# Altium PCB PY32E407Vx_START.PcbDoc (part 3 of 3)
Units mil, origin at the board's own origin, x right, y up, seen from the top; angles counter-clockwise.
Board outline 5249.65 x 2929.09 mil, 4 copper layers (Top Layer, GND, POWER, Bottom Layer); 239 components, 235 nets, 934 pads, 637 vias.
Unrouted connection lines stored in the file: 84.
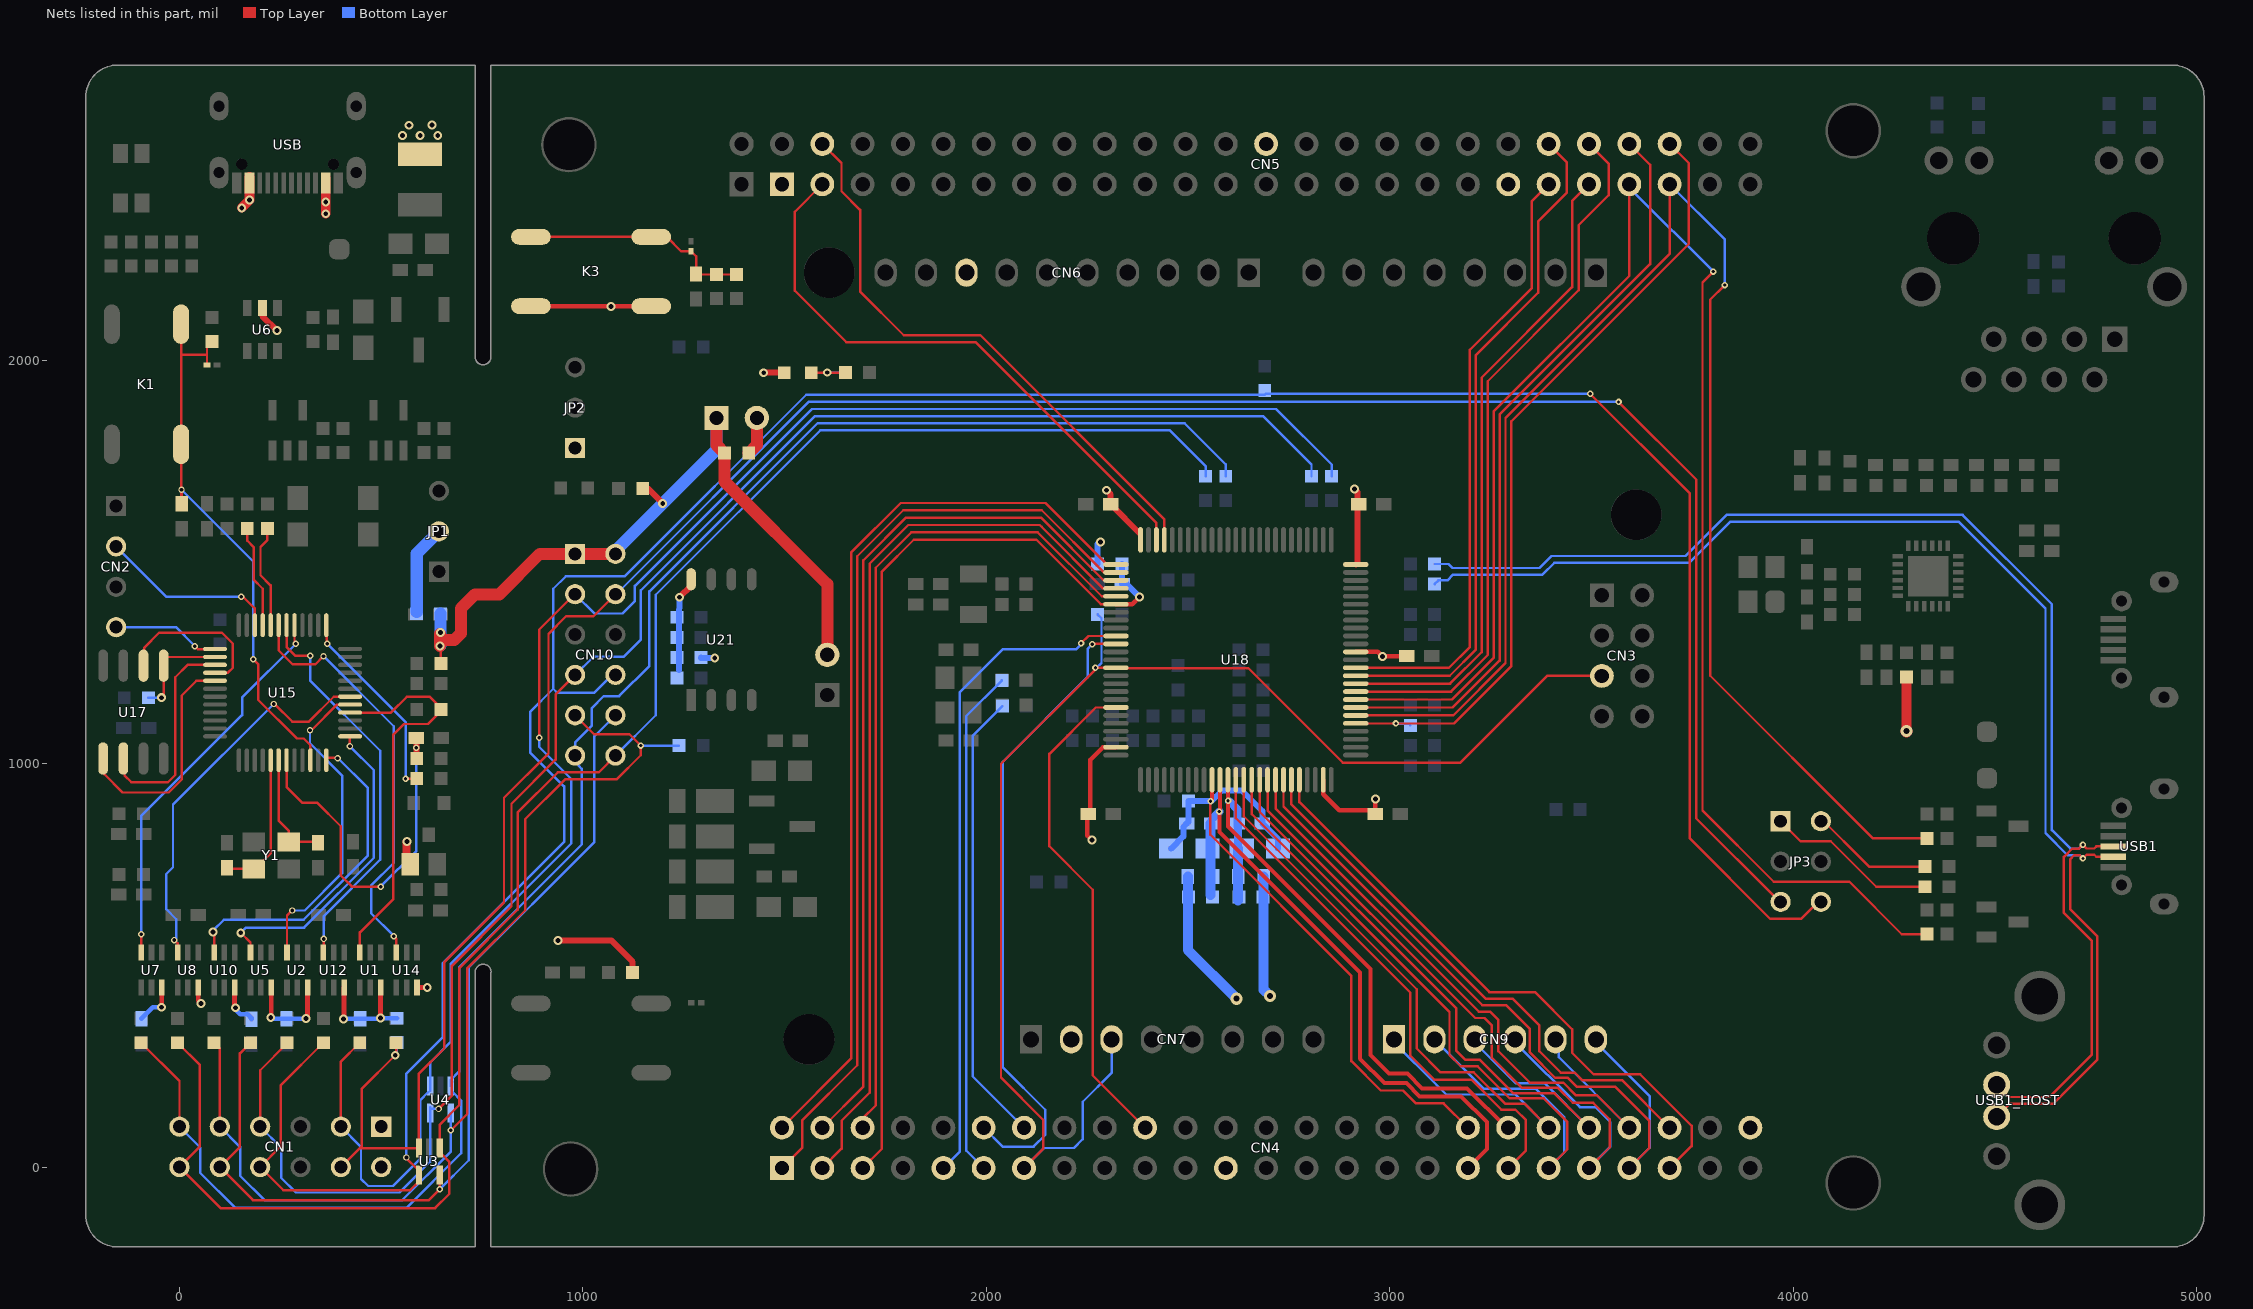
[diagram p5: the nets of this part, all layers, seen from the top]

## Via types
v1: diameter 22, hole 12, Top Layer to Bottom Layer, tented both sides, 398 vias
v2: diameter 16, hole 8, Top Layer to Bottom Layer, tented both sides, 111 vias
v3: diameter 20, hole 10, Top Layer to Bottom Layer, tented both sides, 54 vias
v4: diameter 16, hole 9, Top Layer to Bottom Layer, tented both sides, 41 vias
v5: diameter 30, hole 15, Top Layer to Bottom Layer, tented both sides, 15 vias
v6: diameter 20, hole 10, Top Layer to Bottom Layer, 9 vias
v7: diameter 15, hole 8, Top Layer to Bottom Layer, tented both sides, 5 vias
v8: diameter 16, hole 8, Top Layer to Bottom Layer, 3 vias
v9: diameter 20, hole 12, Top Layer to Bottom Layer, tented both sides, 1 vias

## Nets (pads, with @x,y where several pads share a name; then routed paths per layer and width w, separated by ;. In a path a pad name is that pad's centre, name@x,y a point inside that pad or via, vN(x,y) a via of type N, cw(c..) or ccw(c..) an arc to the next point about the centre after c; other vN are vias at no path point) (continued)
PD8: CN5.46 R58.2 U18.55 | length 1977.9
  Top Layer w6: U18.55@2915.24,1099.61 2915.58,1099.28 3014.72,1099.28 v2(3014.83,1099.38) 3014.93,1099.28 3158.28,1099.28 3301,1241.99 3301,1848.33 3740.4,2287.73 3740.4,2488.25 CN5.46@3693.11,2535.55
  Bottom Layer w6: v2(3014.83,1099.38) 3015.62,1098.59 3046.5,1098.59 R58.2@3050.5,1094.59
PD9: CN5.45 R93.1 U18.56 | length 3787.8
  Top Layer w6: U18.56@2915.24,1119.29 3156.8,1119.29 3286.29,1248.78 3286.29,1856.09 3693.11,2262.91 CN5.45@3693.11,2435.55 ; v2(3829.84,2185.75) 3793.7,2149.61 3793.7,1217.69 4196.8,814.59 R93.1@4330.5,814.59 4338,814.59 R93.1@4343,819.59
  Bottom Layer w6: CN5.45@3693.11,2435.55 3829.84,2298.81 v2(3829.84,2185.75)
PD10: CN5.44 U18.57 | length 1860.7
  Top Layer w6: U18.57@2915.24,1138.98 3155.29,1138.98 3271.57,1255.27 3271.57,1864.73 3644.7,2237.86 3644.7,2483.95 CN5.44@3593.11,2535.55
PD11: CN5.43 R85.1 U18.58 | length 4034.5
  Top Layer w6: U18.58@2915.24,1158.66 3153.67,1158.66 3256.86,1261.85 3256.86,1872.32 3593.11,2208.57 CN5.43@3593.11,2435.55 ; v2(3801.32,2219.18) 3774.5,2192.36 3774.5,883.29 3950.9,706.89 4138.6,706.89 4268.4,577.09 R85.1@4330.5,577.09
  Bottom Layer w6: CN5.43@3593.11,2435.55 3601.15,2435.55 3601.15,2419.35 v2(3801.32,2219.18)
PD12: CN5.42 U18.59 | length 1775.2
  Top Layer w6: U18.59@2915.24,1178.35 3151.56,1178.35 3242.14,1268.94 3242.14,1947.44 3467.9,2173.19 3467.9,2334.67 3541.7,2408.47 3541.7,2486.95 CN5.42@3493.11,2535.55
PD13: CN5.41 U18.60 | length 1613.9
  Top Layer w6: U18.60@2915.24,1198.03 3149.14,1198.03 3227.43,1276.32 3227.43,1956.62 3451.5,2180.69 3451.5,2393.94 CN5.41@3493.11,2435.55
PD14: CN5.40 U18.61 | length 1689.1
  Top Layer w6: U18.61@2915.24,1217.72 3147.93,1217.72 3212.71,1282.51 3212.71,2012.16 ; 3212.77,2012.16 3367.22,2166.62 3367.22,2343.8 3437.8,2414.37 3437.8,2490.85 CN5.40@3393.11,2535.55
PD15: CN5.39 U18.62 | length 1531.4
  Top Layer w6: U18.62@2915.24,1237.4 3146.31,1237.4 3198,1289.09 3198,2025.49 3351.5,2178.99 3351.5,2393.94 CN5.39@3393.11,2435.55
PE0: CN5.4 U18.97 | length 1443.5
  Top Layer w6: CN5.4@1593.11,2535.55 1640.59,2488.07 1640.59,2418.41 1686.8,2372.2 1686.8,2169.49 1794.99,2061.3 1984.79,2061.3 2440.83,1605.26 U18.97@2440.83,1554.33
PE1: CN5.3 U18.98 | length 1468.2
  Top Layer w6: CN5.3@1593.11,2435.55 1525,2367.44 1525,2171.89 1652.6,2044.29 1972.8,2044.29 2421.15,1595.94 U18.98@2421.15,1554.33
PE2: CN4.2 U18.1 | length 2266.5
  Top Layer w6: CN4.2@1493.11,97.55 1664.52,268.96 1664.52,1522.61 1787.68,1645.77 2146.58,1645.77 2299.04,1493.31 U18.1@2320.76,1493.31
PE3: CN4.1 U18.2 | length 2345.4
  Top Layer w6: CN4.1@1493.11,-2.45 1543,47.44 1543,115.59 1679.79,252.38 1679.79,1513.68 1793.68,1627.58 2136.94,1627.58 2290.88,1473.63 U18.2@2320.76,1473.63
PE4: CN4.4 U18.3 | length 2182.4
  Top Layer w6: CN4.4@1593.11,97.55 1695.05,199.49 1695.05,1503.98 1800.45,1609.38 2135,1609.38 2290.44,1453.94 U18.3@2320.76,1453.94
PE5: CN4.3 U18.4 | length 2261.5
  Top Layer w6: CN4.3@1593.11,-2.45 1641.1,45.54 1641.1,114.85 1710.32,184.07 1710.32,1495.3 1806.2,1591.18 2132.13,1591.18 2136.59,1586.72 2289.05,1434.26 U18.4@2320.76,1434.26
PE6: CN4.6 U18.5 | length 2098.2
  Top Layer w6: CN4.6@1693.11,97.55 1693.11,120.4 1725.59,152.88 1725.59,1485.09 1813.49,1572.99 2127.1,1572.99 2285.52,1414.57 U18.5@2320.76,1414.57
PE7: CN4.37 U18.38 | length 1352.4
  Top Layer w6: U18.38@2618,959.85 2618,914.55 2618,864.29 3050.5,431.79 3050.5,275.86 3109.75,216.61 3201.69,216.61 3276.2,142.09 3311,142.09 3336.8,116.29 3336.8,41.24 CN4.37@3293.11,-2.45
PE8: CN4.40 CN9.1 U18.39 | length 1729.7
  Top Layer w6: U18.39@2637.69,959.85 2637.69,869.22 3066.2,440.71 3066.2,294.09 3125.58,234.71 3207.48,234.71 3285.1,157.09 3333.56,157.09 CN4.40@3393.11,97.55
  Bottom Layer w6: CN9.1@3010.11,316.55 3010.11,309.05 3116.3,202.85 3139.26,179.89 3310.76,179.89 CN4.40@3393.11,97.55
PE9: CN4.39 CN9.2 U18.40 | length 1923.1
  Top Layer w6: U18.40@2657.37,959.85 2657.37,874.64 3147.4,384.61 3147.4,277.79 3175.21,249.99 3217.21,249.99 3296.6,170.59 3380.6,170.59 3439.6,111.59 3439.6,44.04 CN4.39@3393.11,-2.45
  Bottom Layer w6: CN9.2@3110.11,316.55 3232.16,194.49 3360.3,194.49 3432.3,122.49 3432.3,36.74 CN4.39@3393.11,-2.45
PE10: CN4.42 CN9.3 U18.41 | length 1659.5
  Top Layer w6: U18.41@2677.06,959.85 2677.06,880.24 3164.41,392.89 3164.41,287.77 3186.78,265.4 3222.99,265.4 3305.8,182.59 3408.06,182.59 CN4.42@3493.11,97.55
  Bottom Layer w6: CN9.3@3210.11,316.55 3210.11,309.05 3311.06,208.09 3382.56,208.09 CN4.42@3493.11,97.55
PE11: CN4.41 CN9.4 U18.42 | length 1891.2
  Top Layer w6: U18.42@2696.74,959.85 2696.74,883.79 3211.23,369.3 3234.4,369.3 3252.45,351.24 3252.45,270.94 3327.2,196.19 3416.2,196.19 3453.1,159.29 3503.5,159.29 3544.56,118.24 3544.56,49 CN4.41@3493.11,-2.45
  Bottom Layer w6: CN9.4@3310.11,316.55 3310.11,309.05 3470.76,148.39 3509,148.39 3546.2,111.19 3546.2,50.64 CN4.41@3493.11,-2.45
PE12: CN4.44 CN9.5 U18.43 | length 1615.7
  Top Layer w6: U18.43@2716.43,959.85 2716.43,888.76 3219.84,385.36 3247.64,385.36 3268.51,364.48 3268.51,286.98 3346.7,208.79 3429.7,208.79 3460.1,178.39 3512.26,178.39 CN4.44@3593.11,97.55
  Bottom Layer w6: CN9.5@3410.11,316.55 3418.11,308.55 3418.11,272.55 CN4.44@3593.11,97.55
PE13: CN4.43 CN9.6 U18.44 | length 1861.8
  Top Layer w6: U18.44@2736.11,959.85 2736.11,893.98 3228.68,401.42 3287.68,401.42 3346.7,342.39 3346.7,283.79 3409.6,220.89 3441.1,220.89 3463.3,198.69 3558.6,198.69 3642.1,115.19 3642.1,46.54 CN4.43@3593.11,-2.45
  Bottom Layer w6: CN9.6@3510.11,316.55 3510.11,309.05 3643.4,175.75 3643.4,47.84 CN4.43@3593.11,-2.45
PE14: CN4.46 U18.45 | length 1367.6
  Top Layer w6: U18.45@2755.8,959.85 2755.8,898.79 3237.12,417.48 3303.72,417.48 3370.4,350.79 3370.4,286.99 3423.7,233.69 3458.2,233.69 3477.1,214.79 3575.86,214.79 CN4.46@3693.11,97.55
PE15: CN4.45 U18.46 | length 1521.2
  Top Layer w6: U18.46@2775.48,959.85 2775.48,904.31 3246.26,433.54 3359.46,433.54 3451.8,341.19 3451.8,282.79 3504.7,229.89 3619.9,229.89 3747.4,102.39 3747.4,51.84 CN4.45@3693.11,-2.45
PF0: CN4.11 R40.1 | length 1262.9
  Bottom Layer w6: CN4.11@1993.11,-2.45 1949.92,40.73 1949.92,1117.72 R40.1@2038.2,1205.99
PF1: CN4.14 R41.1 | length 1127.9
  Bottom Layer w6: R41.1@2039.3,1142.19 1965.68,1068.57 1965.68,224.97 CN4.14@2093.11,97.55
PF2: CN4.20 U18.19 | length 1237.3
  Top Layer w6: U18.19@2320.76,1138.98 2270.85,1138.98 2155.8,1023.94 2155.8,794.99 2263.5,687.29 2263.5,227.15 CN4.20@2393.11,97.55
PF3: CN4.9 U18.10 | length 1642.7
  Top Layer w6: v2(2234.42,1298.19) 2252.38,1316.15 U18.10@2320.76,1316.15
  Bottom Layer w6: CN4.9@1893.11,-2.45 1934.17,38.61 1934.17,1177.16 2040.61,1283.59 2195.53,1283.59 2223.07,1283.59 2232.84,1293.36 2234.42,1294.94 v2(2234.42,1298.19)
PF4: CN4.12 U18.11 | length 1594
  Top Layer w6: v2(2262.22,1295.61) 2263.08,1296.46 U18.11@2320.76,1296.46
  Bottom Layer w6: CN4.12@1993.11,97.55 2039.86,50.79 2116.9,50.79 2145.6,79.49 2145.6,141.99 2040.7,246.89 2040.7,1004.35 2250.45,1214.1 2250.45,1283.84 v2(2262.22,1295.61)
PF5: CN3.5 CN4.13 CN7.3 R54.2 U18.14 | length 3438.5
  Top Layer w6: CN4.13@2093.11,-2.45 2140.2,44.64 2140.2,117.39 2035.9,221.69 2035.9,999.39 2272.2,1235.69 v2@2270.63,1237.27 ; v2(2270.1,1237.27) v2@2270.63,1237.27 ; CN3.5@3525.12,1217.14 3389.25,1217.14 3174.5,1002.39 2882.92,1002.39 2648.72,1236.59 2321.57,1236.59 U18.14@2320.76,1237.4 2320.62,1237.27 v2@2270.63,1237.27
  Bottom Layer w6: CN4.13@2093.11,-2.45 2142.75,47.19 2216.7,47.19 2238.7,69.19 2238.7,161.89 2310.11,233.3 CN7.3@2310.11,316.55 ; v2(2270.1,1237.27) 2272.77,1237.27 2285,1249.49 2285,1360.09 R54.2@2275.5,1369.59
PYLK_KEY: C5.2 K1.2 R14.1 U11.1 U15.10 | length 1409.8
  Top Layer w6: K1.2@4,2089 4,2013.39 ; v4(5,1678.59) 5.5,1678.09 C5.2@5.5,1644 ; C5.2@5.5,1643.81 C5.2@5.5,1644 ; U11.1@68.2,1988 68.2,2013.35 ; R14.1@68.2,2038.7 68.2,2013.35 ; v2(182.8,1258.49) 194.9,1246.39 194.9,1158.25 291.15,1062 307.84,1062 323.91,1045.92 323.91,1008.86 U15.10@324.4,1008.37 ; 4,2013.39 K1.2@4,1791 4,1645.5 C5.2@5.5,1644 ; 4,2013.39 4.04,2013.35 68.2,2013.35
  Bottom Layer w6: v4(5,1678.59) 182.8,1500.79 v2(182.8,1258.49) v2@181.4,1257.09
PYLK_NRST: C24.2 R35.1 U15.7 | length 904.2
  Top Layer w6: U15.7@265.34,1008.18 265.34,941.65 303.74,903.25 340.69,903.25 399.5,844.45 399.5,722.91 427.38,695.03 v4(498.55,695.03)
  Top Layer w15: C24.2@587,1063 587,1029.88 587,1014 R35.1@588,1013
  Bottom Layer w6: v4(498.55,695.03) 587,783.48 v4(587,1039.09)
PYLK_OSCIN: C18.2 U15.5 Y1.3 | length 324.3
  Top Layer w6: C18.2@118,741.6 120.46,739.14 Y1.3@183.99,739.14 ; Y1.3@207.55,736.66 Y1.3@207.55,736.73 ; Y1.3@207.55,758.83 225.97,777.25 U15.5@225.97,1008.37
PYLK_OSCOUT: C23.2 U15.6 Y1.1 | length 291.3
  Top Layer w6: U15.6@245.66,1008.18 245.66,858.97 270.61,834.02 Y1.1@270.61,806.07 346.86,806.07 C23.2@348.7,807.9
PYLK_SPI_CS: R34.1 U15.38 U17.1 | length 258.5
  Top Layer w6: v1(-44.96,1163.25) -39.3,1168.91 U17.1@-39.3,1242.5 -39.3,1256.69 -31.91,1264.08 U15.38@88.18,1264.08
  Bottom Layer w6: R34.1@-77,1163 -45.21,1163 v1(-44.96,1163.25)
PYLK_SPI_MISO: U15.40 U17.2 | length 400.1
  Top Layer w6: U17.2@-89.3,1242.5 -87.63,1244.17 -87.63,1286.77 -50.4,1324 105.36,1324 131.9,1297.46 131.9,1237.16 119.95,1225.21 88.68,1225.21 U15.40@88.18,1224.71
PYLK_SPI_MOSI: U15.41 U17.5 | length 569.9
  Top Layer w6: U17.5@-189.3,1012.5 -186.24,1009.44 -186.24,973.64 -140.8,928.2 -26.75,928.2 5.5,960.45 5.5,1168.55 41.98,1205.03 U15.41@88.18,1205.03
PYLK_SPI_SCK: U15.39 U17.6 | length 536.9
  Top Layer w6: U17.6@-139.3,1012.5 -136.24,1009.44 -136.24,970.64 -119.1,953.5 -28.79,953.5 -10.5,971.79 -10.5,1213.73 20.17,1244.4 U15.39@88.18,1244.4
SWD_SCK: CN2.4 U15.37 | length 267.6
  Top Layer w6: v4(38,1291) 45.23,1283.77 U15.37@88.18,1283.77
  Bottom Layer w6: CN2.4@-157,1338 -9,1338 v4(38,1291)
SWD_SDA: CN2.2 U15.34 | length 448.8
  Top Layer w6: v4(153,1413) 158,1413 186.6,1384.4 U15.34@186.6,1342.82
  Bottom Layer w6: CN2.2@-157,1538 -32,1413 v4(153,1413)
T_RESET: CN1.9 CN10.9 R17.2 R72.1 U4.4 | length 2545.1
  Top Layer w6: R17.2@85.57,308 100,293.57 CN1.9@100,115.48 ; v4(672.5,91.1) 713.57,132.18 713.57,493.07 857.03,636.52 857.03,862.42 955.4,960.79 1083.3,960.79 1143,1020.49 v2(1143,1044.59) 1115.1,1072.49 1027.6,1072.49 CN10.9@980.5,1119.59
  Bottom Layer w6: CN1.9@100,100 150.2,49.8 150.2,-21.5 210.64,-81.94 552.24,-81.94 672.5,38.32 v4(672.5,91.1) v4(672.5,91.1) 672.54,133.49 U4.4@672.59,133.54 ; v2(1143,1044.59) R72.1@1238,1044.59
T_RESETa: U10.3 U15.12 | length 823
  Top Layer w6: v1(83.4,582.2) 85.72,579.88 U10.3@85.72,531.35 ; U15.12@363.77,1008.37 363.77,1012.53 365.91,1014.67 390.24,1014.67 v4(391.72,1013.18)
  Bottom Layer w6: v1(83.4,582.2) 83.4,586.5 109.9,613 307.69,613 467,772.31 467,939.09 392.91,1013.18 v4(391.72,1013.18)
T_RTCK_DTRa: U5.3 U15.13 | length 791.5
  Top Layer w6: v1(151.7,580.5) 176.07,556.13 U5.3@176.07,531.35 ; v4(422.48,1042.59) 422.48,1066.89 U15.13@422.82,1067.23
  Bottom Layer w6: v1(151.7,580.5) 164.59,593.39 308.7,593.39 481.36,766.05 481.36,983.71 v4(422.48,1042.59)
T_RTCK_VCP_DTR: CN1.10 CN10.10 R9.2 U3.5 | length 2323.6
  Top Layer w6: R9.2@175.86,308 149.7,281.84 149.7,49.7 CN1.10@100,0 181.9,-81.9 618.1,-81.9 v4(644.59,-55.41) 644.59,-27.21 640.72,-23.34 U3.5@644.59,-19.46
  Bottom Layer w6: v4(644.59,-55.41) 717,17 717,493.79 1028.4,805.19 1028.4,1067.49 CN10.10@1080.5,1119.59
T_TCK_SWCLK: CN1.7 CN10.7 R6.2 R71.1 U4.5 | length 4394.2
  Top Layer w6: CN1.7@200,115.48 200,240 R6.2@268,308 ; v4(642,144) 675,177 675,498.69 822.8,646.49 822.8,900.19 932.3,1009.69 932.3,1171.39 CN10.7@980.5,1219.59
  Bottom Layer w6: CN1.7@200,100 251.8,48.2 251.8,-26.4 288.4,-63 545,-63 621.41,13.41 U4.5@621.41,144 ; U4.5@621.41,147.87 625.28,144 v4(642,144) ; CN10.7@980.5,1219.59 1025.3,1264.39 1100.3,1264.39 1143.6,1307.69 1143.6,1429.51 1575.09,1860.99 2685.57,1860.99 2805.5,1741.07 R71.1@2805.5,1712.09
T_TCK_SWCLKa: U2.3 U15.17 | length 785
  Top Layer w6: U2.3@266.41,531.35 266.41,623 v4(279.2,635.79) ; v4(323.42,1082.68) 327.03,1082.68 390.32,1145.97 U15.17@422.82,1145.97
  Bottom Layer w6: v4(279.2,635.79) 310.46,635.79 403.2,728.53 403.2,970.4 323.42,1050.19 v4(323.42,1082.68)
T_TDI_VCP_TX: CN1.8 CN10.8 JP3.6 R21.2 R75.1 U3.4 | length 7060.8
  Top Layer w6: R21.2@356.43,308 250.5,202.07 250.5,50.5 CN1.8@200,0 257.22,-57.22 571.78,-57.22 U3.4@592,-37 ; v4(562.51,23.64) 562.51,21.53 589.54,-5.49 U3.4@593.41,-19.46 ; v2(3496.1,1916.59) 3743.1,1669.59 3743.1,814.39 3942.5,614.99 4018.9,614.99 JP3.6@4068,664.09
  Bottom Layer w6: v4(562.51,23.64) 562.51,231.51 652,321 652,504.79 953.1,805.89 953.1,943.29 868.9,1027.49 868.9,1127.79 926.45,1185.34 ; CN10.8@1080.5,1219.59 1072.3,1219.59 1027.7,1174.99 936.8,1174.99 926.45,1185.34 ; v2(3496.1,1916.59) 2692.2,1916.59 2689.6,1913.99 1553.29,1913.99 1103.19,1463.89 957.15,1463.89 926.45,1433.19 926.45,1185.34
T_TDI_VCP_TXa: U12.3 U15.30 | length 987.8
  Top Layer w6: U15.30@265.34,1342.82 265.34,1288.53 286.53,1267.35 v4(323.75,1267.35) ; U12.3@356.75,531.35 357.25,531.85 357.25,564.8 v4(357.76,565.31)
  Bottom Layer w6: v4(323.75,1267.35) 323.75,1205.64 497.61,1031.79 497.61,761.86 357.76,622.01 v4(357.76,565.31)
T_TDO_SWO: CN1.11 CN10.11 R12.2 R73.1 U4.3 | length 4409.4
  Top Layer w6: R12.2@-95,308 0,213 CN1.11@0,115.48
  Bottom Layer w6: CN1.11@0,100 51.6,48.4 51.6,-14.4 138.51,-101.31 562.33,-101.31 698,34.36 698,165.02 U4.3@677.67,185.36 ; U4.3@672.59,200.46 U4.3@672.59,207.72 ; U4.3@676.46,211.6 U4.3@672.59,207.72 ; R73.1@2593,1712.09 2593,1741.24 2490.91,1843.33 1581.41,1843.33 1164.6,1426.52 1164.6,1242.09 1089.49,1166.99 1051.57,1166.99 1022.2,1137.61 1022.2,1094.19 980.5,1052.49 980.5,1019.08 988.92,1010.66 988.92,994.86 997.1,986.68 997.1,799.39 693,495.29 693,236.62 672.59,216.21 U4.3@672.59,207.72
T_TDO_SWOa: U7.3 U15.29 | length 971.7
  Top Layer w6: v4(-95,577) v4(-95,577) U7.3@-94.96,531.35 ; U15.29@285.03,1342.82 285.03,1302.87 288.4,1299.5 v4(288.4,1296.79)
  Bottom Layer w6: v4(-95,577) -95,869.78 155.3,1120.08 155.3,1163.69 v4(288.4,1296.79)
T_TMS_SWDIO: CN1.3 CN10.3 R2.2 R70.1 U4.1 | length 4375.5
  Top Layer w6: CN1.3@400,115.48 400,261.29 R2.2@446.71,308 ; v2(891.6,1064.09) 891.6,1332.27 978.93,1419.59 CN10.3@980.5,1419.59
  Bottom Layer w6: CN1.3@400,100 449.91,50.09 449.91,-29.23 467.68,-47 529,-47 596.97,20.97 596.97,166.16 U4.1@616.12,185.31 ; U4.1@621.41,189.15 U4.1@621.41,200.46 621.41,259.41 672,310 672,503.09 971.4,802.49 971.4,961.19 891.6,1040.99 v2(891.6,1064.09) ; CN10.3@980.5,1419.59 1028.3,1371.79 1097.8,1371.79 1128.8,1402.79 1128.8,1440.27 1567.19,1878.66 2717.89,1878.66 2855.5,1741.05 R70.1@2855.5,1712.09
T_TMS_SWDIOa: R31.1 U1.3 U15.16 | length 980.6
  Top Layer w6: U15.16@422.82,1126.29 524.2,1126.29 563.09,1165.18 620.91,1165.18 652,1134.09 616,1098.09 556.5,1098.09 530,1071.59 530,664.63 447.09,581.73 U1.3@447.09,531.35
T_TRST_RTSa: U8.3 U15.18 | length 975.4
  Top Layer w6: v4(-12.67,562.56) -4.31,554.21 -4.31,531.66 U8.3@-4.62,531.35 ; v4(233.47,1147.57) 235.74,1147.57 279.35,1103.96 320.66,1103.96 382.36,1165.66 U15.18@422.82,1165.66
  Bottom Layer w6: v4(-12.67,562.56) -8,567.23 -8,614.19 -32.91,639.09 -32.91,726.19 -16,743.09 -16,898.1 v4(233.47,1147.57)
T_TRST_VCP_RTS: CN1.12 CN10.12 R13.2 R76.1 U3.1 | length 4444
  Top Layer w6: R13.2@-4.71,308 50.7,252.59 50.7,50.7 CN1.12@0,0 101.62,-101.62 633.38,-101.62 669,-66 669,12.96 U3.1@651.29,30.67 ; U3.1@644.59,33.91 644.59,104.59 693,153 693,492.49 838,637.49 838,878.39 937.6,977.99 1038.9,977.99 CN10.12@1080.5,1019.59 ; U3.1@646.07,30.24 U3.1@648.46,27.84
  Bottom Layer w6: CN10.12@1080.5,1019.59 1180.5,1119.59 1180.5,1418.18 1587.98,1825.66 2454.83,1825.66 2543,1737.49 R76.1@2543,1712.09
T_VCP_RX: CN1.4 CN10.4 JP3.5 R22.1 R24.2 U3.3 | length 6245.8
  Top Layer w6: CN1.4@400,0 447,47 ; R24.2@537,308 537,279.26 v1(534.69,276.95) 451.4,193.66 451.4,51.4 447,47 ; CN10.4@1080.5,1419.59 1026.1,1365.19 958.3,1365.19 914.5,1321.39 914.5,1025.29 804.3,915.09 804.3,655.69 656.38,507.77 656.38,294.38 593.41,231.41 U3.3@593.41,47.46 592.94,47 447,47 ; v2(3566.62,1896.14) 3759,1703.76 3759,863.79 3958.7,664.09 JP3.5@3968,664.09
  Bottom Layer w6: v1(534.69,276.95) 538.7,280.96 R22.1@538.7,308.7 ; CN10.4@1080.5,1419.59 1082.57,1419.59 1559.3,1896.33 3566.43,1896.33 v2(3566.62,1896.14)
T_VCP_RXa: U14.3 U15.31 | length 1052.3
  Top Layer w6: U15.31@245.66,1342.82 245.66,1280.89 280.65,1245.9 336.54,1245.9 v4(356.96,1266.33) ; v4(530.59,571.9) 537.44,565.05 U14.3@537.44,531.35
  Bottom Layer w6: v4(356.96,1266.33) 531.02,1092.27 531.02,753.72 475,697.7 475,629.04 530.59,573.45 v4(530.59,571.9)
TVDD: C11.2 C12.2 C13.2 C14.2 CN1.1 CN1.2 CN10.1 CN10.2 JP4.2 JP5.1 R15.2 R16.2 R22.2 R33.2 R110.1 R112.2 U1.6 U2.6 U5.6 U7.6 U8.6 U10.6 U12.6 U14.6 | length 2811.8
  Top Layer w6: R16.2@648,1238 v1@648,1288.5
  Top Layer w12: v1@-43.78,396.48 U7.6@-43.78,444.73 ; U8.6@46.56,444.73 46.56,412.54 53.66,405.44 v1(53.66,405.36) ; U10.6@136.68,444.51 136.68,396.79 v1(138.76,394.71) ; v1(226.14,370.36) 227.25,371.46 U5.6@227.25,444.73 ; v1(313.66,368.22) 317.59,372.15 U2.6@317.59,444.73 ; v1(406.55,366.75) 407.93,368.13 U12.6@407.93,444.73 ; U1.6@498.28,444.73 498.28,369.22 v1(498.5,369) ; U14.6@588.62,444.73 588.89,445 v1(614,445) ; v1(645.4,1291.1) v1@648,1288.5 ; v1@645.4,1321 648,1323.6 v1(646.5,1325.1) ; R112.2@1148,1682.09 R112.2@1160.02,1682.09
  Top Layer w15: R112.2@1160.02,1682.09 v1(1197.52,1644.59)
  Top Layer w20: v1(563.45,806.47) 562.41,805.43 562.41,760.12 R15.2@572.04,750.5
  Top Layer w30: v1(645.4,1291.1) 645.4,1306.05 ; v1@645.4,1321 645.4,1306.05 ; CN10.2@1080.5,1519.59 CN10.1@980.5,1519.59 893,1519.59 792.5,1419.09 731.9,1419.09 697.53,1384.72 697.53,1322.64 680.93,1306.05 645.4,1306.05 ; JP5.1@1330.89,1856.71 1330.89,1789.21 R110.1@1350.89,1769.21 1350.89,1699.21 1605.5,1444.59 JP4.2@1605.5,1269.59
  Bottom Layer w12: C12.2@-94.3,367.9 -66.1,396.1 v1(-44.16,396.1) ; v1(138.76,394.71) 138.76,391.04 150.98,378.82 168.7,378.82 178.2,369.32 C13.2@178.2,366.3 ; v1(226.14,370.36) 228.8,367.7 C11.2@265.7,367.7 313.14,367.7 v1(313.66,368.22) ; v1(406.55,366.75) 407.5,367.7 C14.2@447.9,367.7 497.2,367.7 v1(498.5,369) 498.8,368.7 R22.2@538.7,368.7 ; v1(645.4,1291.1) 646.1,1291.1 647.1,1292.1 v1@646.5,1292.7 ; v1(646.5,1325.1) v1@647.1,1325.7 ; CN10.2@1080.5,1519.59 CN10.2@1080.5,1527.58
  Bottom Layer w30: v1@646.5,1292.7 v1(646.5,1325.1) ; v1@647.1,1325.7 R33.2@647.1,1371.3 ; CN10.2@1080.5,1527.58 v1(1197.52,1644.59) 1330.89,1777.97 JP5.1@1330.89,1856.71
TVDD*: JP1.2 R33.1 | length 222.8
  Bottom Layer w30: R33.1@588,1375.5 588,1520.5 JP1.2@643,1575.5
TVDD_DISCHARGE_EN: R18.2 U15.25 | length 489.6
  Top Layer w6: U15.25@363.77,1342.82 364.66,1341.93 364.66,1298.44 v2(366,1297.09) ; v2(560.31,962.53) 587.53,962.53 R18.2@588,963
  Bottom Layer w6: v2(366,1297.09) 560.31,1102.78 v2(560.31,962.53)
USB1_D+: R86.2 USB1.3 USB1_HOST.3 | length 3293.3
  Top Layer w6: USB1_HOST.3@4503.65,203.69 4533.75,173.59 4634.6,173.59 4738.81,277.81 4738.81,561.28 4670.2,629.89 4670.2,768.7 4690.7,789.19 4707.57,789.19 v2(4717.22,798.85) v2@4717.22,798.67 ; v2@4717.22,796.12 v2@4717.22,798.67 ; USB1.3@4792.65,794.59 4750.59,794.59 4745.48,789.48 4726.4,789.48 v2@4717.22,798.67
  Bottom Layer w6: R86.2@3110.5,1494.59 3145.38,1494.59 3155.3,1484.67 3370.48,1484.67 3400.1,1514.29 3732.1,1514.29 3833.9,1616.09 4419,1616.09 4640.4,1394.69 4640.4,835.09 4686.29,789.21 4707.58,789.21 v2(4717.22,798.85)
USB1_D-: R87.2 USB1.2 USB1_HOST.2 | length 3294.2
  Top Layer w6: USB1_HOST.2@4503.65,124.99 4535.05,156.39 4643,156.39 4753,266.39 4753,571.69 4686.4,638.29 4686.4,763.5 4695.59,772.69 4709.28,772.69 v2(4717.22,764.75) ; v2@4717.22,764.93 4726.4,774.11 4745.48,774.11 4750.59,769 USB1.2@4792.65,769
  Bottom Layer w6: R87.2@3110.5,1444.59 3119.86,1453.95 3142.45,1453.95 3156.59,1468.09 3378,1468.09 3407.25,1497.34 3741.25,1497.34 3842.7,1598.79 4410.2,1598.79 4624.52,1384.47 4624.52,827.47 4679.27,772.72 4709.26,772.72 v2(4717.22,764.75)
USB1_ID: JP3.2 R84.1 | length 319.7
  Top Layer w6: JP3.2@4059,873.09 4187.5,744.59 R84.1@4325.5,744.59
USB1_VBUS: JP3.1 R89.1 | length 424.8
  Top Layer w6: JP3.1@3968,857.09 4017.7,807.39 4092.19,807.39 4204.99,694.59 R89.1@4325.5,694.59
USB_DM: R10.2 U15.32 | length 257.7
  Top Layer w6: R10.2@218,1583 218,1554.08 200.79,1536.87 200.79,1466.58 225.97,1441.4 U15.32@225.97,1342.82
USB_DP: R11.2 U15.33 | length 256
  Top Layer w6: R11.2@168,1583 168,1552.45 183.78,1536.68 183.78,1455.75 206.29,1433.23 U15.33@206.29,1342.82
USER_KEY: C39.2 K3.1 R79.1 R82.2 U20.1 | length 574
  Top Layer w6: K3.1@871,2305.29 K3.1@1169,2305.29 1207.8,2305.29 1243.3,2269.79 U20.1@1268,2269.79 1280.5,2257.29 C39.2@1280.5,2213.09 1281.5,2212.09 R82.2@1330.5,2212.09 R79.1@1380.5,2212.09
USER_LED: LED2.2 R80.1 R81.1 | length 123.1
  Top Layer w6: LED2.2@1566,1968.59 1605.15,1968.59 v6(1605.32,1968.76) 1641.83,1968.76 1642,1968.59 R81.1@1643,1969.59
  Bottom Layer w6: v6(1605.32,1968.76) 1649.67,1968.76 R80.1@1650.5,1969.59
VBAT: C58.2 CN4.5 R111.2 U18.6 | length 2348.9
  Top Layer w6: CN4.5@1693.11,-2.45 1740.85,45.29 1740.85,1475.9 1819.75,1554.79 2123.62,1554.79 2283.51,1394.89 U18.6@2320.76,1394.89
  Top Layer w11: U18.6@2320.76,1394.89 2361.2,1394.89 v1(2379.1,1412.79)
  Bottom Layer w6: C58.2@2335.5,1445.59 C58.2@2336.5,1444.59 C58.2@2347.3,1444.59 ; v1@2377.19,1414.71 v1(2379.1,1412.79)
  Bottom Layer w15: C58.2@2335.5,1445.59 R111.2@2335.5,1494.59 ; C58.2@2347.3,1444.59 v1@2377.19,1414.71
VBUS_PYLK: FUSE1.1 U6.5 USB.A4 USB.A9 USB.B4 USB.B9 | length 245.4
  Top Layer w15: U6.5@205.5,2128.65 205.5,2108.9 240.94,2073.47 v1(241.93,2073.47)
  Top Layer w24: v1(154.2,2377.18) v1(173.54,2396.51) USB.B4@173.54,2454.3 ; v1(362.48,2362.54) v1(362.48,2391.55) USB.B9@362.48,2451.95
  other v1: 552.96,2556.2 596.52,2556.2 640.08,2556.2 568.71,2581.79 625.88,2582.12
VCCA: C35.2 C36.2 CN4.38 L1.2 R74.2 U18.37 | length 1502.5
  Top Layer w10: U18.37@2598.32,959.85 2598.32,911.82 2601.97,908.17 2601.97,907.06 2599.1,904.19 2599.1,844.1 2951.9,491.3 2951.9,277.43 2998.04,231.3 3043.45,231.3 3079.52,195.23 3191.29,195.23 3288.97,97.55 CN4.38@3293.11,97.55
  Bottom Layer w20: v2@2600.7,905.79 2602.72,905.79 2622.49,886.03 C36.2@2622.49,845.61 ; C35.2@2623.5,789.09 C36.2@2623.5,845.61
  Bottom Layer w25: R74.2@2623.5,660.49 2623.5,719.59 C35.2@2623.5,789.09
  other v2: 2598.78,907.56
VDD: C30.2 C31.2 C32.2 C33.2 C34.2 CN4.23 CN4.50 CN5.1 CN5.26 CN5.37 CN7.2 JP2.1 JP5.2 K3.2 L1.1 L2.1 LED2.1 R57.1 R74.1 R77.1 R88.1 R97.1 R110.2 R111.1 U18.24 U18.49 U18.64 U18.75 U18.100 | length 2535.2
  Top Layer w6: U18.75@2890.24,1493.21 2894.92,1493.21 U18.75@2897.6,1495.9
  Top Layer w11: K3.2@846,2133.49 846.4,2133.09 1143.6,2133.09 K3.2@1144,2133.49 ; C32.2@2250.2,875.01 2250.2,821.31 v1(2261.34,810.17) ; C32.2@2252.54,875.01 2256.98,879.45 2256.98,1008.87 2288.66,1040.55 U18.24@2320.76,1040.55 ; U18.49@2834.54,959.85 2834.54,923.95 2874.1,884.39 2957.42,884.39 2963.61,878.2 2963.61,911.1 v1(2964.3,911.79) ; U18.64@2915.24,1276.77 2969.87,1276.77 v1(2981.6,1265.04) 2982.86,1266.29 C30.2@3041.8,1266.29
  Top Layer w15: v1(937.8,561.7) 1070,561.7 1123,508.7 R57.1@1123,482.09 ; v1(1447.8,1968.59) LED2.1@1499,1968.59 ; v1(2297.33,1677.44) 2307.7,1667.07 C34.2@2307.7,1642.49 U18.100@2379.99,1570.21 ; v1(2911.66,1680.25) 2919.6,1672.31 2919.6,1497.67 U18.75@2915.24,1493.31
  Top Layer w25: v5(4280.5,1080.69) R97.1@4280.5,1214.59
  Top Layer w30: R110.2@1410.89,1769.21 1430.89,1789.21 JP5.2@1430.89,1856.71 ; v5@4279.7,1079.89 v5(4280.5,1080.69)
  Bottom Layer w15: R88.1@1292.5,1262.5 1292.92,1262.08 1326.18,1262.08 v1(1326.6,1261.67) ; R111.1@2275.5,1494.59 2275.5,1544.44 2280.18,1549.12 v1(2282.22,1549.12)
  Bottom Layer w25: L2.1@2499,719.59 2499,538.09 v5(2619.9,417.19) ; L1.1@2687,719.59 2687,439.51 v5(2702.4,424.1)
  other v1: 1069,2133.09
VDD_FLASH: R48.2 R49.2 R88.2 R90.2 U21.8 | length 238.1
  Top Layer w6: U21.8@1268,1441.14 U21.8@1268,1456.7
  Top Layer w15: v1(1238.93,1412.07) U21.8@1268,1441.14
  Bottom Layer w6: 1238,1382.09 1236.7,1383.39 1238.93,1385.62
  Bottom Layer w15: 1238,1232.09 1238,1282.09 1238,1332.09 1238,1382.09 ; 1238.93,1385.62 v1(1238.93,1412.07)
VREF+: C37.2 C38.2 CN4.35 CN6.8 L2.2 R77.2 U18.36 | length 1554.8
  Top Layer w6: CN4.35@3193.11,12.55 CN4.35@3193.11,14.55
  Top Layer w10: v2(2577.06,880.92) 2577.06,830.46 2925.46,482.06 2925.46,268.38 2985.9,207.94 3040.52,207.94 3073.09,175.37 3176.41,175.37 3240.52,111.26 3240.52,44.96 CN4.35@3193.11,-2.45 ; v2@2578.63,882.49 2578.63,933.77 U18.36@2578.63,959.85
  Bottom Layer w6: v2(2577.06,880.92) v2@2578.48,879.5
  Bottom Layer w20: C38.2@2558.6,862.46 v2(2577.06,880.92)
  Bottom Layer w25: R77.2@2555.5,674.59 2555.5,726.59 2555.5,789.09 C38.2@2555.5,851.59
VSSA: C35.1 C36.1 C37.1 C38.1 CN4.36 R78.1 U18.35 | length 1659.9
  Top Layer w6: v2(2555.42,906.8) 2554.42,905.8 2554.42,823.9 2904.42,473.9 2904.42,262.42 2977.15,189.69 3032.3,189.69 3064.28,157.71 3132.94,157.71 CN4.36@3193.11,97.55 ; v2@2557.26,906.8 v2@2558.94,908.48
  Top Layer w10: v2@2558.94,908.48 U18.35@2558.94,959.85
  Bottom Layer w15: C37.1@2457.6,789.09 2487.83,819.33 2487.83,842.83 C38.1@2496.6,851.59 2500.4,855.39 R78.1@2500.4,907.19 2500.79,906.8 v2(2555.42,906.8) ; v2@2556.87,907.19 2557.26,906.8 2583.7,933.24 2632.75,933.24 2683.6,882.39 C36.1@2683.6,851.59 2722.6,812.59 C35.1@2722.6,789.09
pads on no net: CN7.1 CN7.8 ETH. ETH.7 U15.42 U15.45 U22.10 USB. USB.A8 USB.B8

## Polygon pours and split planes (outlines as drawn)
GND on Bottom Layer "Top-GND" (solid, remove dead copper, pour order 1): -238,2679.29 -185.7,2731.59 4963.3,2731.59 5018.1,2676.79 5018.1,-151.31 4971.6,-197.81 -167.7,-197.81 -236.1,-129.41 -236.1,2677.59
GND on Top Layer "Top-GND" (solid, remove dead copper, pour order 0): -237.8,2679.49 -186.2,2731.09 4964.1,2731.09 5017.8,2677.39 5017.8,-152.91 4972.71,-198 -169.11,-198 -237.8,-129.31
3V3_PYLK on POWER (split plane): 151 vertices, not listed, extent -211.9,-177.9 745.42,2711
VDD on POWER (split plane): 3815.31,1132.29 3815.66,1129.68 3816.66,1127.25 3818.27,1125.16 3820.36,1123.56 3822.79,1122.55 3825.4,1122.21 4502.9,1122.21 4505.51,1122.55 4507.94,1123.56 4510.03,1125.16 4511.64,1127.25 4512.64,1129.68 4512.99,1132.29 4512.99,1224.61 4891.2,1224.61 4893.81,1224.95 4896.24,1225.96 4898.33,1227.56 4899.93,1229.65 4900.94,1232.08 4901.29,1234.69 4901.29,2107.89 4902.7,2107.71 4997.55,2107.71 4997.51,-119.26 4997.51,-125.04 4995.26,-136.37 4990.84,-147.04 4984.42,-156.64 4976.25,-164.81 4966.64,-171.23 4955.97,-175.65 4944.64,-177.9 4938.87,-177.9 792.04,-177.9 792.39,483.04 792.29,484.02 792.29,485.02 791.91,488.86 791.72,489.83 791.62,490.81 791.34,491.75 791.14,492.72 790.77,493.63 790.48,494.58 787.54,501.67 785.68,505.15 783.63,507.65 783.18,508.19 777.75,513.63 776.42,514.72 774.71,516.12 773.33,516.86 771.23,517.98 765.59,520.32 765.59,612.36 771.45,614.79 773.06,615.66 774.92,616.65 777.97,619.15 783.5,624.69 786,627.73 787.86,631.21 790.86,638.44 792,642.21 792.39,646.13 792.39,650.05 792.03,653.65 792.03,1352.45 792.39,1356.05 792.39,1359.96 792,1363.88 790.86,1367.65 787.86,1374.89 786,1378.36 783.5,1381.41 777.97,1386.95 774.92,1389.45 771.45,1391.3 765.59,1393.73 765.59,1425.5 765.34,1427.41 771.09,1429.79 774.57,1431.65 777.61,1434.15 783.15,1439.69 785.65,1442.73 787.51,1446.21 790.5,1453.44 791.65,1457.21 792.03,1461.13 792.03,1465.05 792.03,1911.05 792.03,1914.96 791.65,1918.88 790.5,1922.65 787.51,1929.89 785.65,1933.36 783.15,1936.41 777.61,1941.95 774.57,1944.45 771.09,1946.3 765.35,1948.68 765.59,1950.5 765.59,1970.95 770.88,1973.14 774.35,1975 777.4,1977.5 782.83,1982.93 785.33,1985.98 787.19,1989.45 790.13,1996.55 790.41,1997.49 790.79,1998.4 790.98,1999.37 791.27,2000.32 791.37,2001.3 791.56,2002.27 791.94,2006.11 791.94,2007.1 792.03,2008.08 792.03,2711 3815.31,2711
TVDD on POWER (split plane): 655.91,1243.18 638,1243.18 635.39,1242.84 632.96,1241.83 630.87,1240.23 629.26,1238.14 628.26,1235.7 627.91,1233.09 627.91,557.09 627.91,-57.31 456.39,-57.31 456.39,284.1 456.04,286.71 455.03,289.14 453.43,291.23 451.34,292.84 448.91,293.84 446.3,294.19 -118.21,294.19 -118.21,460.31 483,460.31 485.61,460.66 488.04,461.67 490.13,463.27 491.73,465.36 492.74,467.79 493.09,470.4 493.09,1346.01 655.91,1346.01
3V3 on POWER (split plane): 1693.21,777.68 1124,777.68 1121.39,777.34 1118.96,776.33 1116.87,774.73 1115.26,772.64 1114.26,770.2 1113.91,767.59 1113.91,669.99 1113.91,568.19 1114.26,565.58 1115.26,563.15 1116.87,561.06 1118.96,559.46 1121.39,558.45 1124,558.11 1344.91,558.11 1344.91,467.39 1345.26,464.78 1346.26,462.35 1347.87,460.26 1349.96,458.66 1352.39,457.65 1355,457.31 2441.51,457.31 2441.51,261.38 2322.59,261.38 2322.59,371.49 2322.24,374.1 2321.23,376.54 2319.63,378.63 2317.54,380.23 2315.11,381.24 2312.5,381.58 988.79,381.58 988.79,866.81 1495.2,866.81 1497.81,867.15 1500.24,868.16 1502.33,869.76 1503.93,871.85 1504.94,874.28 1505.29,876.89 1505.29,1217.81 1693.21,1217.81
VBUS_PYLK on POWER (split plane): 712.47,2048.89 127.09,2048.89 127.09,2711 712.47,2711
5V_USB2_START on POWER (split plane): 4588.6,680.58 3191,680.58 3188.39,680.24 3188.01,680.08 1134.09,680.08 1134.09,757.51 1697.02,757.51 1698.26,756.56 1700.69,755.55 1703.3,755.21 1705.91,755.55 1708.34,756.56 1709.58,757.51 4497.7,757.51 4500.31,757.85 4502.74,758.86 4504.83,760.46 4506.43,762.55 4507.44,764.98 4507.79,767.59 4507.79,874.81 4588.6,874.81
5V_USB1_START on POWER (split plane): 4595.27,578.78 3304.3,578.78 3301.69,578.44 3301.31,578.28 1134.09,578.28 1134.09,659.91 3215.5,659.91 3218.11,660.25 3218.49,660.41 4595.27,660.41
5V on POWER (split plane): 3691.41,1006.19 3691.76,1003.58 3692.76,1001.15 3694.37,999.06 3696.46,997.46 3698.89,996.45 3701.5,996.11 4715.91,996.11 4715.91,479.58 3414.26,479.58 3413.5,479.68 2570.8,479.68 2568.19,479.34 2565.76,478.33 2563.67,476.73 2562.06,474.64 2561.06,472.2 2560.71,469.59 2560.71,277.24 2560.71,263.68 2461.69,263.68 2461.69,467.39 2461.34,470.01 2460.33,472.44 2458.73,474.53 2456.64,476.13 2454.21,477.14 2451.6,477.48 1365.09,477.48 1365.09,558.11 3315,558.11 3317.61,558.45 3317.99,558.61 4605.36,558.61 4607.97,558.95 4610.4,559.96 4612.49,561.56 4614.09,563.65 4615.1,566.08 4615.45,568.69 4615.45,660.55 4615.1,663.16 4614.09,665.6 4612.49,667.69 4610.4,669.29 4608.71,669.99 4608.77,670.49 4608.77,884.89 4608.43,887.51 4607.42,889.94 4605.82,892.03 4603.73,893.63 4601.3,894.64 4598.69,894.98 4495.6,894.98 4492.99,894.64 4490.56,893.63 4488.47,892.03 4486.86,889.94 4485.86,887.51 4485.51,884.89 4485.86,882.28 4486.86,879.85 4487.61,878.88 4487.61,777.68 3532.69,777.68 3532.69,1471.71 3691.41,1471.71
VREF+ on POWER (split plane): 1992.91,943.99 1993.26,941.38 1994.26,938.95 1995.87,936.86 1997.96,935.26 2000.39,934.25 2003,933.91 2642.31,933.91 2642.31,848.08 1907.89,848.08 1907.89,2269.61 1992.91,2269.61
ETH_VDD on POWER (split plane): 4881.11,1244.78 4396.49,1244.78 4396.49,1309.31 4782.5,1309.31 4785.11,1309.65 4787.54,1310.66 4789.63,1312.26 4791.23,1314.35 4792.24,1316.78 4792.59,1319.39 4792.59,1874.09 4792.24,1876.7 4791.23,1879.14 4789.63,1881.23 4787.54,1882.83 4785.11,1883.84 4782.5,1884.18 4545.69,1884.18 4545.69,2107.71 4881.11,2107.71
ETH_VDDA on POWER (split plane): 4955.81,2708.74 4966.48,2704.32 4976.09,2697.91 4984.26,2689.74 4990.68,2680.13 4995.1,2669.46 4997.4,2657.87 4997.55,2652.09 4997.55,2127.88 4902.7,2127.88 4900.09,2127.54 4897.66,2126.53 4896.95,2125.99 4896.24,2126.53 4893.81,2127.54 4891.2,2127.88 4535.6,2127.88 4532.99,2127.54 4530.56,2126.53 4528.47,2124.93 4526.86,2122.84 4525.86,2120.41 4525.51,2117.79 4525.51,1874.09 4525.86,1871.48 4526.86,1869.05 4528.47,1866.96 4530.56,1865.36 4532.99,1864.35 4535.6,1864.01 4772.41,1864.01 4772.41,1329.48 4386.4,1329.48 4383.79,1329.14 4381.36,1328.13 4379.27,1326.53 4377.66,1324.44 4376.66,1322.01 4376.31,1319.39 4376.31,1234.69 4376.66,1232.08 4377.66,1229.65 4379.27,1227.56 4381.36,1225.96 4383.79,1224.95 4386.4,1224.61 4492.81,1224.61 4492.81,1142.38 3835.49,1142.38 3835.49,2711 4938.71,2711 4944.48,2711
GND on GND (split plane): 712.47,2008.08 712.57,2007.1 712.57,2006.11 712.95,2002.27 713.14,2001.3 713.23,2000.32 713.52,1999.37 713.71,1998.4 714.09,1997.49 714.38,1996.55 717.32,1989.45 719.17,1985.98 721.67,1982.93 727.1,1977.5 730.15,1975 733.62,1973.14 740.72,1970.2 744.49,1969.06 748.41,1968.68 756.09,1968.68 760.01,1969.06 763.78,1970.2 770.88,1973.14 774.35,1975 777.4,1977.5 782.83,1982.93 785.33,1985.98 787.19,1989.45 790.13,1996.55 790.41,1997.49 790.79,1998.4 790.98,1999.37 791.27,2000.32 791.37,2001.3 791.56,2002.27 791.94,2006.11 791.94,2007.1 792.03,2008.08 792.03,2711 4938.71,2711 4944.48,2711 4955.81,2708.74 4966.48,2704.32 4976.09,2697.91 4984.26,2689.74 4990.68,2680.13 4995.1,2669.46 4997.4,2657.87 4997.55,2652.09 4997.51,-119.26 4997.51,-125.04 4995.26,-136.37 4990.84,-147.04 4984.42,-156.64 4976.25,-164.81 4966.64,-171.23 4955.97,-175.65 4944.64,-177.9 4938.87,-177.9 792.04,-177.9 792.39,483.04 792.29,484.02 792.29,485.02 791.91,488.86 791.72,489.83 791.62,490.81 791.34,491.75 791.14,492.72 790.77,493.63 790.48,494.58 787.54,501.67 785.68,505.15 783.63,507.65 783.18,508.19 777.75,513.63 776.42,514.72 774.71,516.12 773.33,516.86 771.23,517.98 764.14,520.92 760.37,522.06 756.45,522.45 748.77,522.45 744.85,522.06 741.07,520.92 733.98,517.98 730.5,516.12 729.13,515 727.46,513.63 722.03,508.19 719.53,505.15 717.67,501.67 714.73,494.58 714.71,494.5 714.67,494.43 714.14,492.62 713.59,490.81 713.58,490.73 713.56,490.65 712.83,486.81 712.66,484.93 712.47,483.05 712.47,-177.9 -153.26,-177.9 -159.04,-177.9 -170.37,-175.65 -181.04,-171.23 -190.64,-164.81 -198.81,-156.64 -205.23,-147.04 -209.65,-136.37 -211.9,-125.04 -211.9,-119.26 -211.9,2652.35 -211.9,2658.13 -209.65,2669.46 -205.23,2680.13 -198.81,2689.74 -190.64,2697.91 -181.04,2704.32 -170.37,2708.74 -159.04,2711 -153.26,2711 712.47,2711

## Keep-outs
Keep-Out Layer:
  lines w5: 732.57,483.05 732.57,-198 -153.26,-198 cw(c-153.26,-119.26) -232,-119.26 -232,2652.35 cw(c-153.26,2652.35) -153.26,2731.09 732.57,2731.09 732.57,2008.08 ccw(c752.25,2008.08) 771.94,2008.08 771.94,2731.09 4938.71,2731.09 cw(c4938.71,2652.35) 5017.45,2652.35 ; 732.57,650.05 732.57,1357.05 ; 732.92,483.05 cw(c752.61,483.05) 772.29,483.05 ; 732.92,650.05 ccw(c752.61,650.05) 772.29,650.05 ; 732.92,1356.05 cw(c752.61,1356.05) 772.29,1356.05 ; 771.94,-198 771.94,483.05 ; 771.94,650.05 771.94,1356.05 ; 772,-198 4938.87,-198 ccw(c4938.87,-119.26) 5017.61,-119.26 ; 5017.65,-119.26 5017.65,2652.35 ; 732.57,1465.05 ccw(c752.25,1465.05) 771.94,1465.05 771.94,1911.05 ccw(c752.25,1911.05) 732.57,1911.05 732.57,1465.05

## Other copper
Top Layer:
  pour cut-out: 431,1616 503,1616 503,1608 431,1608
  pour cut-out: 233.5,1675.4 329.8,1675.4 329.8,1596.9 258,1596.9 258,1573 233.5,1573
  pour cut-out: 18.7,1675 57.2,1675 57.2,1589.83 18.7,1589.83
  pour cut-out: 1378.2,888.8 1475.9,888.8 1475.9,681.1 1369.3,681.1 1369.3,888.9 1378.2,888.9
  region net 3V3_PYLK: 480.5,1963.7 438.9,1922.1 375.2,1922.1 349.4,1947.9 349.4,1991.9 365.1,2007.6 365.1,2045 374.9,2054.8 456.6,2054.8 480.5,2030.9
  region net VBUS_PYLK: 651.3,2517.4 651.3,2572.6 631.1,2592.8 564.1,2592.8 541.7,2570.4 541.7,2520.8 554.4,2508.1 642,2508.1
Bottom Layer:
  pour cut-out: 2566.4,765.8 2566.4,654.1 2613.1,654.1 2613.1,764.5
POWER (plane layer: these items are gaps in the copper):
  lines w20: 117,2725.2 117,2038.8 743,2038.8 ; 750.6,1818.7 750.6,2718.09 ; 755.5,500.5 755.5,613 ; 755.5,1388 755.5,1425.5 ; 755.5,1950.5 755.5,1975.5 ; 978.7,371.49 2312.5,371.49 2312.5,252.69 2313.9,251.29 2451.6,251.29 ; 978.7,372.39 978.7,876.89 1495.2,876.89 1495.2,1227.89 1703.3,1227.89 1703.3,765.29 ; 1355,568.19 1355,467.39 2451.6,467.39 2451.6,253.59 2570.8,253.59 2570.8,277.24 2570.8,469.59 3413.5,469.59 ; 3191,670.49 4598.69,670.49 4598.69,884.89 4495.6,884.89 ; 3215.5,669.99 1124,669.99 ; 3304.3,568.69 4605.36,568.69 4605.36,660.55 ; 3315,568.19 1124,568.19 1124,669.99 ; 3405.5,469.49 4726,469.49 4726,1006.19 3701.5,1006.19 3701.5,1481.79 3522.6,1481.79 3522.6,770.49 ; 4497.7,884.89 4497.7,767.59 3113.7,767.59 1124,767.59 1124,669.99 ; 4502.9,1234.29 4502.9,1132.29 3825.4,1132.29 3825.4,2724.09 4981,2724.09 5015.1,2689.99 5015.1,2117.79 4902.7,2117.79 ; -128.3,284.1 446.3,284.1 446.3,-67.4 638,-67.4 638,557.09 638,1233.09 666,1233.09 666,1356.09 483,1356.09 483,470.4 -128.3,470.4 -128.3,284.1 ; 1897.8,837.99 2652.4,837.99 2652.4,943.99 2003,943.99 2003,2279.69 1897.8,2279.69 1897.8,837.99 ; 4386.4,1234.69 4461.5,1234.69 4891.2,1234.69 4891.2,2117.79 4535.6,2117.79 4535.6,1874.09 4782.5,1874.09 4782.5,1319.39 4386.4,1319.39 4386.4,1234.69

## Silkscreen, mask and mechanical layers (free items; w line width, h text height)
Top Overlay:
  drawing of 1086 lines, arcs and shapes, not listed
  text "E0" at 1581.05,2596.18 h60 r45
  text "B8" at 1681.08,2596.15 h60 r45
  text "B6" at 1781.31,2596.16 h60 r45
  text "D5" at 2079.06,2596.14 h60 r45
  text "D3" at 2179.33,2596.16 h60 r45
  text "A10" at 2867.96,2596.16 h60 r45
  text "A8" at 2978.64,2596.13 h60 r45
  text "D10" at 3570.03,2596.17 h60 r45
  text "D8" at 3680.7,2596.15 h60 r45
  text "B4" at 1880.68,2595.69 h60 r45
  text "D7" at 1979.02,2595.68 h60 r45
  text "D1" at 2281.38,2595.68 h60 r45
  text "A14" at 2568.75,2595.69 h60 r45
  text "A12" at 2767.74,2595.69 h60 r45
  text "D14" at 3370.19,2595.71 h60 r45
  text "D12" at 3469.81,2595.7 h60 r45
  text "B14" at 3770.65,2595.71 h60 r45
  text "B12" at 3870.26,2595.71 h60 r45
  text "C8" at 3079.12,2589.03 h60 r45
  text "C6" at 3180.15,2589.07 h60 r45
  text "GND" at 1461.47,2588.39 h60 r45
  text "C12" at 2368.74,2588.65 h60 r45
  text "C10" at 2469.65,2588.56 h60 r45
  text "GND" at 3263.47,2588.39 h60 r45
  text "GND" at 1364.47,2587.39 h60 r45
  text "VDD" at 2661.62,2584.57 h60 r45
  text "51" at 3980.46,2508.08 h60 r45
  text "52" at 3984.08,2403.9 h60 r45
  text "E1" at 1584.86,2313.89 h60 r45
  text "B9" at 1682.42,2313.73 h60 r45
  text "B3" at 1982.45,2312.76 h60 r45
  text "D9" at 3683.45,2311.76 h60 r45
  text "D2" at 2279.84,2310.7 h60 r45
  text "D0" at 2380.53,2310.84 h60 r45
  text "A9" at 2981.98,2310.29 h60 r45
  text "C9" at 3082.12,2310.03 h60 r45
  text "D6" at 2081.48,2309.79 h60 r45
  text "B7" at 1781.77,2308.54 h60 r45
  text "B5" at 1881.81,2308.33 h60 r45
  text "D4" at 2180.72,2308.67 h60 r45
  text "C7" at 3182.91,2305.07 h60 r45
  text "B13" at 3873.9,2292.21 h60 r45
  text "D11" at 3574.81,2290.65 h60 r45
  text "C11" at 2472.67,2289.21 h60 r45
  text "D13" at 3472.93,2289.24 h60 r45
  text "A11" at 2873.31,2288.17 h60 r45
  text "A13" at 2670.46,2287.78 h60 r45
  text "B15" at 3773.58,2287.12 h60 r45
  text "D15" at 3372.43,2285.19 h60 r45
  text "A15" at 2570.27,2284.27 h60 r45
  text "E5V" at 1372.15,2281.55 h60 r45
  text "VDD" at 1464.62,2278.57 h60 r45
  text "VDD" at 3265.62,2278.57 h60 r45
  text "GND" at 2764.47,2274.39 h60 r45
  text "8" at 2668.94,2125.94 h60 r90
  text "7" at 2827.94,2126.38 h60 r90
  text "2" at 3330.14,2125.73 h60 r90
  text "4" at 3129.37,2124.61 h60 r90
  text "12" at 2269.19,2100.19 h60 r90
  text "13" at 2169.76,2099.8 h60 r90
  text "~9" at 2568.84,2094.69 h60 r90
  text "~6" at 2928.91,2094.75 h60 r90
  text "~5" at 3029.24,2094.47 h60 r90
  text "~3" at 3230.09,2094.75 h60 r90
  text "~11" at 2368.62,2072.33 h60 r90
  text "~10" at 2468.74,2065 h60 r90
  text "SCL" at 1769.22,2051.18 h60 r90
  text "USER" at 1004,2048.88 h60
  text "SDA" at 1869.82,2043.3 h60 r90
  text "GND" at 2069.69,2037.69 h60 r90
  text "TX   1" at 3430.16,2011.59 h60 r90
  text "AREF" at 1969.07,2010.46 h60 r90
  text "RX   0" at 3530.94,2008.83 h60 r90
  text "GND" at 1023,1963.88 h60
  text "DIGITAL(~=PWM)" at 2418,1947.21 h60
  text "BOOT0" at 1023,1865.88 h60
  text "IDD" at 1486,1844.9 h60
  text "VDD" at 1023,1761.9 h60
  text "5V" at 547,1650.35 h50
  text "V" at -113.31,1620.67 h60
  text "VDD" at 514,1556.08 h50
  text "D" at -108.97,1519.82 h60
  text "VDD" at 829.5,1500.32 h60
  text "VDD" at 1122.13,1500.4 h60
  text "3V3" at 527,1458.3 h50
  text "G" at -112.46,1421.21 h60
  text "JLCJLCJLCJLC" at 2419.51,1413.98 h60
  text "SWD" at 819.85,1400.31 h60
  text "RX" at 1122.13,1400.73 h60
  text "5V" at 3684.17,1398.22 h60
  text "MISO" at 3336,1396.88 h60
  text "C" at -110.28,1319.16 h60
  text "GND" at 826.23,1300.33 h60
  text "GND" at 1122.13,1299.71 h60
  text "MOSI" at 3684.18,1297.68 h60
  text "SCK" at 3358.99,1296.88 h60
  text "VDD" at 1655,1242.9 h60
  text "SWC" at 819.12,1200.35 h60
  text "TX" at 1122.13,1200.07 h60
  text "GND" at 3684.2,1197.16 h60
  text "NRST" at 3325.91,1196.88 h60
  text "3V3" at 1662.2,1145.39 h60
  text "NRST" at 798.92,1100.36 h60
  text "DTR" at 1122.13,1100.4 h60
  text "PB10" at 3680.53,1098.16 h60
  text "NSS" at 3363.34,1096.88 h60
  text "SWO" at 816.41,1000.38 h60
  text "RTS" at 1122.13,999.38 h60
  text "ID" at 4119.45,845.56 h60
  text "USB1" at 3585.86,844.88 h60
  text "VBUS" at 3773.16,844.88 h60
  text "PA10" at 4119.45,744.93 h60
  text "GPIO" at 3583.01,744.77 h60
  text "PA9" at 3821.37,744.05 h60
  text "TX" at 4119.42,645.12 h60
  text "VCP" at 3604.13,644.65 h60
  text "RX" at 3846.36,644.01 h60
  text "PY32E407-START V2.0" at 2240,570.46 h80
  text "PY-LINK V2.0" at -194.27,414.09 h80 r270
  text "NC" at 2130.22,376.44 h60 r90
  text "IOREF" at 2230.24,376.44 h60 r90
  text "RESET" at 2330.26,376.44 h60 r90
  text "3.3V" at 2429.76,376.44 h60 r90
  text "5V" at 2529.14,376.44 h60 r90
  text "GND" at 2629.17,376.44 h60 r90
  text "GND" at 2729.19,376.44 h60 r90
  text "NC" at 2829.22,376.44 h60 r90
  text "AN0" at 3028.94,376.4 h60 r90
  text "AN1" at 3129.31,376.4 h60 r90
  text "AN2" at 3229.69,376.4 h60 r90
  text "AN3" at 3330.76,376.4 h60 r90
  text "AN4" at 3430.98,376.4 h60 r90
  text "AN5" at 3531.87,376.4 h60 r90
  text "NRST" at 80.77,281.58 h60 r270
  text "SWO" at -19.22,264.09 h60 r270
  text "SWC" at 180.75,261.38 h60 r270
  text "SWD" at 380.72,260.65 h60 r270
  text "GND" at 280.73,254.27 h60 r270
  text "VDD" at 480.72,251 h60 r270
  text "E6" at 1682.55,156.96 h60 r45
  text "A3" at 2682.01,156.93 h60 r45
  text "A5" at 2781.86,156.91 h60 r45
  text "E8" at 3383.52,156.95 h60 r45
  text "E10" at 3473.05,156.98 h60 r45
  text "B10" at 3771.95,156.97 h60 r45
  text "E2" at 1503.62,156.48 h60 r45
  text "E4" at 1581.8,156.49 h60 r45
  text "F4" at 1983.93,156.5 h60 r45
  text "F2" at 2384.05,155.91 h60 r45
  text "A1" at 2483.86,156.45 h60 r45
  text "A7" at 2881.19,156.45 h60 r45
  text "B1" at 3085.29,156.48 h60 r45
  text "E12" at 3572.37,156.51 h60 r45
  text "E14" at 3671.3,156.51 h60 r45
  text "VDD" at 3863.62,156.5 h60 r45
  text "C5" at 2982.04,150.96 h60 r45
  text "C13" at 1770.6,150.52 h60 r45
  text "C0" at 2182.19,150.11 h60 r45
  text "C2" at 2282.28,150.2 h60 r45
  text "C15*" at 1864.03,149.45 h60 r45
  text "F1*" at 2076.53,149.53 h60 r45
  text "GND" at 2564.47,149.39 h60 r45
  text "VSSA" at 3154.05,141.96 h60 r45
  text "VCCA" at 3250.96,140.88 h60 r45
  text "NRST" at 946,137.88 h60
  text "1" at 1413.61,85.47 h60 r45
  text "49" at 3968.56,72.07 h60 r45
  text "2" at 1405.6,-23.54 h60 r45
  text "50" at 3977.29,-38.99 h60 r45
  text "RTS" at -20.22,-41.63 h60 r270
  text "DTR" at 80.8,-41.63 h60 r270
  text "TX" at 180.47,-41.63 h60 r270
  text "GND" at 280.12,-41.63 h60 r270
  text "RX" at 381.14,-41.63 h60 r270
  text "VDD" at 480.8,-41.63 h60 r270
  text "A2" at 2489.37,-130.77 h60 r45
  text "F3" at 1891.02,-131.55 h60 r45
  text "F5" at 2091.2,-131.65 h60 r45
  text "C1" at 2191.81,-132.13 h60 r45
  text "E3" at 1489.55,-133.81 h60 r45
  text "E5" at 1589.53,-133.91 h60 r45
  text "B0" at 2991.12,-133.93 h60 r45
  text "B2" at 3090.64,-133.73 h60 r45
  text "E7" at 3289.4,-133.7 h60 r45
  text "E9" at 3389.65,-133.86 h60 r45
  text "A0" at 2390.26,-136.78 h60 r45
  text "A4" at 2688.5,-136.63 h60 r45
  text "A6" at 2788.72,-136.86 h60 r45
  text "C3" at 2289.9,-137.37 h60 r45
  text "C4" at 2889.37,-137.26 h60 r45
  text "F0*" at 1983.81,-143.25 h60 r45
  text "E11" at 3481.19,-149.66 h60 r45
  text "B11" at 3881.75,-149.86 h60 r45
  text "E13" at 3578.88,-154.91 h60 r45
  text "E15" at 3678.98,-155.12 h60 r45
  text "VDD" at 2572.62,-165.43 h60 r45
  text "GND" at 3771.47,-166.61 h60 r45
  text "C14*" at 1770.03,-168.05 h60 r45
  text "VBAT" at 1660.5,-186.55 h60 r45
  text "VREF+" at 3150.06,-197.99 h60 r45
